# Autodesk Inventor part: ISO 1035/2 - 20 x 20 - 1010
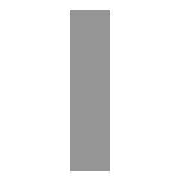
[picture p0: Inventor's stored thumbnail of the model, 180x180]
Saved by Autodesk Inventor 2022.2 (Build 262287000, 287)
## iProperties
IsCustomPart: 1
Created: 2025-02
Part Number: ISO 1035/2 - 20 x 20 - 1010
Material: Acciaio, Dolce
Description: Barre in acciaio laminate a caldo - Parte 2: barre quadre
Document SubType Name: Modeling
Standard: ISO 1035/2
Designer: 18907419
Standard Revision: First edition 1980-10-15
Standards Organization: ISO
Language: it-IT
Size Designation: 20x 20
Categories: <MemberInstance><Categories><Category DisplayName="Forme strutturali" InternalName="089c4875-fa83-4c05-b084-43b9cc11f5ed" Mnemonic="GRDR"><CategoryParameter Dis
Stock Number: 20x 20
Density: 7.85 g/cm^3
Appearance: Semilucidato
_CCFamilyMember: 168
_CCFamilyDisplayName: ISO 1035/2 - 1980 - Barre in acciaio laminate a caldo - Parte 2: barre quadre
_FrameMemberDoc: Frame Member File
_Version: 15.0.0
_GetPNFromCC: 1
G_L: 1010,000 mm
G_W: 20,000 mm
G_H: 20,000 mm
+735E3BF1-8EBF-4594-9FF7-BC9BC0BA5294+CUTDETAIL1: Angolo retto 45,00 gr
+B7A49465-4835-4679-87DF-84439F735B6F+CUTDETAIL2: Angolo retto 45,00 gr
Author: 18907419
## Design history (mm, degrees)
node "Piano iniziale"
node "Piano finale"
sketch "Schizzo"
  geometry: L1 (10, -10)-(-10, -10); L2 (-10, -10)-(-10, 10); L3 (-10, 10)-(10, 10); L4 (10, 10)-(10, -10); L5 (-6, 0)-(8, 0); L6 (0, -30)-(0, 40); L7 (0, 54)-(0, -44) reference; L8 (-14, 0)-(14, 0) reference
  constraints: 12 end point, 2 collinear, 2 parallel, 1 horizontal, 1 perpendicular
  dimensions: "d0" = 20 distance between parallel lines of L3 L1 (= G_W); "d1" = 20 distance between parallel lines of L4 L2 (= G_H); "d4" = 10 distance between parallel lines of L6 L4 (= 0.5 x d1); "d5" = 10 distance between parallel lines of L5 L3 (= 0.5 x d0)
extrude "Corpo" new body sketch "Schizzo" stored distance "d2" = 1010 (= G_L); taper "d3" = 0 deg
node "Driven Length"
  sketch "Sketch3"
    geometry: L1 (0, 0)-(10, 0) reference
    constraints: 2 end point, 1 horizontal
  workplane "Work Plane3"
  sketch "Sketch4"
    geometry: L1 (-2, -10)-(12, -10) reference; L2 (-2, 1000)-(12, 1000) reference
    dimensions: "d9" = 1010 dimension on L1 L2 (derived)
node "Piano di lavoro4"
feature "Divisione1"
node "Piano di lavoro5"
feature "Divisione2"
body "Solid1"
other parameters: "G_W" = 20 [user parameter; used in 1 equation term], "G_H" = 20 [user parameter; used in 1 equation term], "G_L" = 1010 (= d9) [user parameter; used in 1 equation term], "G_OFFSET_END" = 0 [user parameter; used in 1 equation term], "d8" = 90 deg
